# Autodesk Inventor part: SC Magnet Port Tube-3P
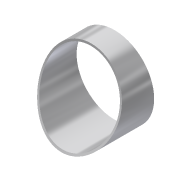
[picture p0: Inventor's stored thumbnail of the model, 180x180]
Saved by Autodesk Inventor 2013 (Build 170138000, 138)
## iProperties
Created: 2012-05
Part Number: SC Magnet Port Tube-3P
Material: Stainless Steel, 316
Document SubType Name: Modeling
Designer: ssc
Mass: 946.545 g
Surface Area: 801.814 cm^2
Volume: 119.062 cm^3
Density: 7.95 g/cm^3
Author: ssc
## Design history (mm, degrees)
sketch "Sketch1"
  geometry: C1 r 70.65 at (0, 0); C2 r 67.246 at (0, 0)
  constraints: 2 centre point, 1 coincident, 1 other
  dimensions: "d0" = 141.3002 diameter of C1; "d1" = 3.4036 radial gap between concentric circles of C2 C1
extrude "Extrusion1" new body sketch "Sketch1" distance "d2" = 152.4; taper "d3" = 0 deg
sketch "Sketch2"
  geometry: L1 (-70.65, 152.4)-(70.65, 152.4) reference; L2 (-70.65, 0)-(70.65, 0) reference; L3 (0, -198.12)-(0, 1188.72) reference; C1 r 476.25 at (165.1, 508)
  constraints: 1 centre point
  dimensions: "d4" = 165.1 distance from line of L3 C1.centre; "d5" = 952.5 diameter of C1; "d6" = 508 distance from line of C1.centre L2
extrude "Extrusion2" cut sketch "Sketch2" stored distance "d7" = 152.4; taper "d8" = 0 deg
body "Solid1"
node "Projected Loop1"
